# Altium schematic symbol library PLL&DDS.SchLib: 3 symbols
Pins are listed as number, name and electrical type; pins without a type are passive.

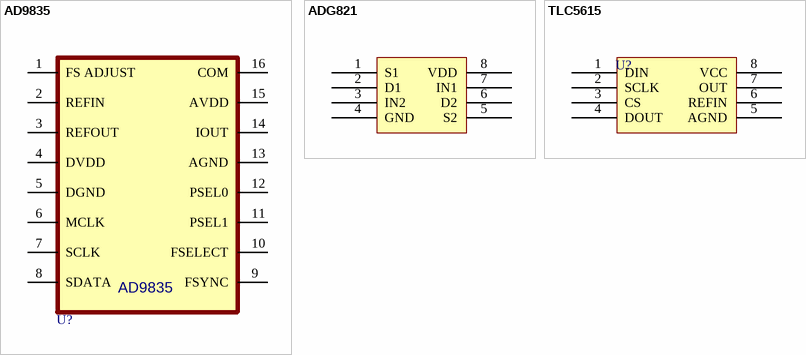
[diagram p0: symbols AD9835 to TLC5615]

## AD9835
designator U?
50 MHz CMOS / Complete DDS
footprint TSSOP-16
pins: 1 FS ADJUST, 2 REFIN, 3 REFOUT, 4 DVDD (power), 5 DGND (power), 6 MCLK, 7 SCLK, 8 SDATA, 9 FSYNC, 10 FSELECT, 11 PSEL1, 12 PSEL0, 13 AGND (power), 14 IOUT, 15 AVDD, 16 COM

## ADG821
designator ?
pins: 1 S1, 2 D1, 3 IN2, 4 GND, 5 S2, 6 D2, 7 IN1, 8 VDD

## TLC5615
designator U?
10bit DA Convertor
footprint SO-8
pins: 1 DIN, 2 SCLK, 3 CS, 4 DOUT, 5 AGND, 6 REFIN, 7 OUT, 8 VCC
